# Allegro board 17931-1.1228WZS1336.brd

Outline 227 x 157 mm; copper layers: TOP, L2GND, L3, L4VCC, L5, L6, L7GND, BOTTOM. Coordinates in mm from the lower left corner of the outline.

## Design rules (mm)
constraint set DEFAULT: min track width 0.127, pair gap 0.102
net group 00_POWER_25M: nets PQ3802_1 PSID_DISABLE#_R_C
net group 00_POWER_1600M: nets XVDD_R1 XVDD_R2
net group CRT_DDI_TX_N0: nets CRT_DDI_TX_N0 DP2_DEMUX_OUT2_D0N
net group CRT_DDI_TX_N1: nets CRT_DDI_TX_N1 DP2_DEMUX_OUT2_D1N
net group CRT_DDI_TX_P0: nets CRT_DDI_TX_P0 DP2_DEMUX_OUT2_D0P
net group CRT_DDI_TX_P1: nets CRT_DDI_TX_P1 DP2_DEMUX_OUT2_D1P
net group DDR4_A_BA_40-MW: nets M_A_BA0 M_A_BA1
net group DDR4_A_BG_40-MW: nets M_A_BG0 M_A_BG1
net group DDR4_A_ODT: nets M_A_DIMA_ODT0 M_A_DIMA_ODT1
net group DDR4_B_BA_40-MW: nets M_B_BA0 M_B_BA1
net group DDR4_B_BG_40-MW: nets M_B_BG0 M_B_BG1
net group DDR4_B_ODT: nets M_B_DIMB_ODT0 M_B_DIMB_ODT1
net group DDR4_VREF_40: nets V_SM_VREF_CNTA V_SM_VREF_CNTB
net group DP2_DEMUX_OUT2_D0-DIFF2: nets DP2_DEMUX_OUT2_D0N_R DP2_DEMUX_OUT2_D0P_R
net group DP2_DEMUX_OUT2_D1-DIFF2: nets DP2_DEMUX_OUT2_D1N_R DP2_DEMUX_OUT2_D1P_R
net group DP_AUX_CON-DIFF1: nets DP2_AUX_C_N DP2_AUX_C_P
net group FBA_REFC0: nets FBA_VREFC0 FBA_VREFC1
net group FBA_VREF: nets FBA_VREF_FET_H FBA_VREF_FET_L
net group GFX_PCIE_TX_C_N0: nets GFX_PCIE_TX_C_N0 GFX_PCIE_TX_N0
net group GFX_PCIE_TX_C_N1: nets GFX_PCIE_TX_C_N1 GFX_PCIE_TX_N1
net group GFX_PCIE_TX_C_N2: nets GFX_PCIE_TX_C_N2 GFX_PCIE_TX_N2
net group GFX_PCIE_TX_C_N3: nets GFX_PCIE_TX_C_N3 GFX_PCIE_TX_N3
net group GFX_PCIE_TX_C_P0: nets GFX_PCIE_TX_C_P0 GFX_PCIE_TX_P0
net group GFX_PCIE_TX_C_P1: nets GFX_PCIE_TX_C_P1 GFX_PCIE_TX_P1
net group GFX_PCIE_TX_C_P2: nets GFX_PCIE_TX_C_P2 GFX_PCIE_TX_P2
net group GFX_PCIE_TX_C_P3: nets GFX_PCIE_TX_C_P3 GFX_PCIE_TX_P3
net group GPU_XTAL-DIFF1: nets 27MHZ_IN 27MHZ_OUT
net group HDMI_DDI_TX_CMC_N0: nets HDMI_DDI_TX_CMC_N0 HDMI_DDI_TX_CON_N0
net group HDMI_DDI_TX_CMC_N1: nets HDMI_DDI_TX_CMC_N1 HDMI_DDI_TX_CON_N1
net group HDMI_DDI_TX_CMC_N2: nets HDMI_DDI_TX_CMC_N2 HDMI_DDI_TX_CON_N2
net group HDMI_DDI_TX_CMC_N3: nets HDMI_DDI_TX_CMC_N3 HDMI_DDI_TX_CON_N3
net group HDMI_DDI_TX_CMC_P0: nets HDMI_DDI_TX_CMC_P0 HDMI_DDI_TX_CON_P0
net group HDMI_DDI_TX_CMC_P1: nets HDMI_DDI_TX_CMC_P1 HDMI_DDI_TX_CON_P1
net group HDMI_DDI_TX_CMC_P2: nets HDMI_DDI_TX_CMC_P2 HDMI_DDI_TX_CON_P2
net group HDMI_DDI_TX_CMC_P3: nets HDMI_DDI_TX_CMC_P3 HDMI_DDI_TX_CON_P3
net group LAN_MDI0_N: nets LAN_MDI0_N MDO0-
net group LAN_MDI0_P: nets LAN_MDI0_P MDO0+
net group LAN_MDI1_N: nets LAN_MDI1_N MDO1-
net group LAN_MDI1_P: nets LAN_MDI1_P MDO1+
net group LAN_MDI2_N: nets LAN_MDI2_N MDO2-
net group LAN_MDI2_P: nets LAN_MDI2_P MDO2+
net group LAN_MDI3_N: nets LAN_MDI3_N MDO3-
net group LAN_MDI3_P: nets LAN_MDI3_P MDO3+
net group M_A_CLK0-DIFF184: nets M_A_CLK0 M_A_CLK#0
net group M_A_CLK1-DIFF185: nets M_A_CLK1 M_A_CLK#1
net group M_A_DQS0-DIFF188: nets M_A_DQS_DN0 M_A_DQS_DP0
net group M_A_DQS1-DIFF188: nets M_A_DQS_DN1 M_A_DQS_DP1
net group M_A_DQS2-DIFF188: nets M_A_DQS_DN2 M_A_DQS_DP2
net group M_A_DQS3-DIFF188: nets M_A_DQS_DN3 M_A_DQS_DP3
net group M_A_DQS4-DIFF188: nets M_A_DQS_DN4 M_A_DQS_DP4
net group M_A_DQS5-DIFF188: nets M_A_DQS_DN5 M_A_DQS_DP5
net group M_A_DQS6-DIFF188: nets M_A_DQS_DN6 M_A_DQS_DP6
net group M_A_DQS7-DIFF188: nets M_A_DQS_DN7 M_A_DQS_DP7
net group M_B_CLK0-DIFF186: nets M_B_CLK0 M_B_CLK#0
net group M_B_CLK1-DIFF187: nets M_B_CLK1 M_B_CLK#1
net group M_B_DQS0-DIFF188: nets M_B_DQS_DN0 M_B_DQS_DP0
net group M_B_DQS1-DIFF188: nets M_B_DQS_DN1 M_B_DQS_DP1
net group M_B_DQS2-DIFF188: nets M_B_DQS_DN2 M_B_DQS_DP2
net group M_B_DQS3-DIFF188: nets M_B_DQS_DN3 M_B_DQS_DP3
net group M_B_DQS4-DIFF188: nets M_B_DQS_DN4 M_B_DQS_DP4
net group M_B_DQS5-DIFF188: nets M_B_DQS_DN5 M_B_DQS_DP5
net group M_B_DQS6-DIFF188: nets M_B_DQS_DN6 M_B_DQS_DP6
net group M_B_DQS7-DIFF188: nets M_B_DQS_DN7 M_B_DQS_DP7
net group MEM_SMBCLK: nets MEM_SMBCLK PCH_SMBCLK
net group MEM_SMBDATA: nets MEM_SMBDATA PCH_SMBDATA
net group NONE_PWR2: nets 5V_AUX_S5 PWR_5V_LDO
net group PCIE_RCOMP-DIFF: nets PCIE_RCOMPN PCIE_RCOMPP
net group PWR_CHG_CSINP-DIFF1: nets PWR_CHG_CSIN_RR PWR_CHG_CSIP_RR
net group PWR_CHG_CSINP-DIFF2: nets PWR_CHG_CSIN_R PWR_CHG_CSIP_R
net group PWR_CHG_CSINP-DIFF3: nets PWR_CHG_CSIN PWR_CHG_CSIP
net group PWR_CHG_CSONP-DIFF1: nets PWR_CHG_CSON_RR PWR_CHG_CSOP_RR
net group PWR_CHG_CSONP-DIFF2: nets PWR_CHG_CSON_R PWR_CHG_CSOP_R
net group PWR_CHG_CSONP-DIFF3: nets PWR_CHG_CSON PWR_CHG_CSOP
net group PWR_VCCGT_ISUMNP_GA-DIFF1: nets PWR_VCCGT_ISUMN_GA PWR_VCCGT_ISUMP_GA
net group PWR_VCCGT_ISUMNP_GB-DIFF1: nets PWR_VCCGT_ISUMN_GB PWR_VCCGT_ISUMP_GB
net group PWR_VCCGT_SENSE-DIFF1: nets VCCGT_SENSE VSSGT_SENSE
net group PWR_VCCSA_ISUMNP-DIFF1: nets PWR_VCCSA_ISUMN_R PWR_VCCSA_ISUMP_R
net group PWR_VCCSA_SENSE-DIFF1: nets VCCSA_SENSE VSSSA_SENSE
net group PWR_VCORE_ISUMNP-DIFF1: nets PWR_VCORE_ISUMN_G PWR_VCORE_ISUMP_G
net group PWR_VCORE_SENSE-DIFF1: nets VCCCORE_SENSE VSSCORE_SENSE
net group PWR_VGA_SENSE-DIFF1: nets VGACORE_GND_SENSE_1 VGACORE_VDD_SENSE_1
net group T8-MW: nets CMP_VIN0 CMP_VIN0_R
net group THERM-DIFF1: nets NCT7718_DXN NCT7718_DXP
net group TYPEC_DPB_AUX-DIFF1: nets TYPEC_DP_AUXN TYPEC_DP_AUXP
net group TYPEC_SBU_AUX-DIFF1: nets USB1_SBU1 USB1_SBU2
net group USB4_USB30_RX-DIFF1: nets USB4_USB30_RX_N USB4_USB30_RX_P
net group USB4_USB30_RX-DIFF2: nets USB4_USB30_RX_C_N USB4_USB30_RX_C_P
net group USB4_USB30_RX-DIFF3: nets USB4_USB30_RX_C_R_N USB4_USB30_RX_C_R_P
net group USB4_USB30_TX-DIFF2: nets USB4_USB30_TX_C_N USB4_USB30_TX_C_P
net group USB4_USB30_TX-DIFF3: nets USB4_USB30_TX_N USB4_USB30_TX_P
net group USB4_USB30_TX-DIFF4: nets USB4_USB30_TX_C_R_N USB4_USB30_TX_C_R_P
net group USB_CC_15M: nets USBC1_CC1_CONN USBC1_CC2_CONN
net group VRAM_10M: nets FBA_SEN0 FBA_SEN2
net group VRAM_DQ_45R: nets FBA_CLK0_MIDPT FBA_CLK1_MIDPT
net group WLAN_PCIE10_RX-DIFF1: nets WLAN_PCIE_RX_N10 WLAN_PCIE_RX_P10
net group WLAN_PCIE10_TX-DIFF1: nets WLAN_PCIE_TX_N10 WLAN_PCIE_TX_P10
net group WLAN_PCIE_TX-DIFF1: nets WLAN_PCIE_TX_CON_N WLAN_PCIE_TX_CON_P
net group XDP_CLK-DIFF1: nets XDP_CLK_CPU_N XDP_CLK_CPU_P
net group 00_POWER_5M: nets 3D3V_LAN_CT2 3V5V_CT1 3V5V_CT2 AON_CT_2 AUD_PC_BEEP AUD_PC_BEEP_C BEEP HDA_SPKR_R KBC_BEEP_R LPS_SW LPS_SW_A LPS_SW_C LPS_SW_D SPKR VGA_CT_1 VGA_NVVDD
net group 00_POWER_10M: nets 1D0V_VCCA_XTAL 1D0V_VCCAMPHYPLL 1D0V_VCCDSW +5V_AVDD +SDC_IN_SW_R1 BMON22 CNV_WT_RCOMP FP_3D3V GSENSOR_CS HW_ACAV_IN0 HW_ACAVIN_NB0 I_BATT LDO1_CAP LDO2_CAP LDO3_CAP MIC_CAP PWR_VGA_NVDD_SS PWR_VGA_NVVDD_VSEN PWR_VGA_NVVDD_VSNS/SS
net group 00_POWER_10M_POWER: nets 3D3V_GSEN2 3D3V_MUX 3D3V_MUX2 3D3V_MUX_VCC AC_IN#_G AD_OFF_R AMBER_LED_BAT BAT_AMBER BAT_WHITE LAN_LED0 LAN_LED0_Q LAN_LED0_R PD_VCCD PWR_1D05V_PFM# PWR_1D05V_SS PWR_1D05V_TON PWR_1D35V_BYP PWR_1D35V_IMAX PWR_3D3V_VOUT PWR_5V_VOUT PWR_CHG_ACIN PWR_CHG_ADP/ACIN PWR_CHG_AIN PWR_CHG_AIN_R PWR_CHG_AMON PWR_CHG_ASGATE PWR_CHG_ASGATE/NTC PWR_CHG_BATGONE PWR_CHG_CMRSC PWR_CHG_COMP PWR_CHG_COMP_R PWR_CHG_DCIN PWR_CHG_DCIN_R PWR_CHG_NTC PWR_CHG_OTGEN PWR_CHG_OTGPG PWR_CHG_PROG PWR_CHG_VBAT1 PWR_VCCGT_COMP PWR_VCCGT_COMP1 PWR_VCCGT_FCCM# PWR_VCCGT_FCCM#_RA PWR_VCCGT_FCCM#_RB PWR_VCCGT_IMON PWR_VCCGT_ISEN1 PWR_VCCGT_ISEN2 PWR_VCCGT_ISUMN PWR_VCCGT_ISUMN_P_1 PWR_VCCGT_ISUMN_P_2 PWR_VCCGT_ISUMN_RC PWR_VCCGT_ISUMNB PWR_VCCGT_ISUMP PWR_VCCGT_NTC PWR_VCCGT_NTC1 PWR_VCCGT_PWMA PWR_VCCGT_PWMA_RA PWR_VCCGT_PWMB PWR_VCCGT_PWMB_RA PWR_VCCGT_RTN PWR_VCCSA_COMP PWR_VCCSA_COMP_RC PWR_VCCSA_FCCM PWR_VCCSA_IMON PWR_VCCSA_ISUMN PWR_VCCSA_ISUMN_P_1 PWR_VCCSA_ISUMN_P_2 PWR_VCCSA_ISUMN_RC PWR_VCCSA_ISUMNB PWR_VCCSA_ISUMP PWR_VCCSA_PWM PWR_VCCSA_RTN PWR_VCORE_COMP PWR_VCORE_COMP1 PWR_VCORE_FCCM# PWR_VCORE_FCCM#_R PWR_VCORE_IMON PWR_VCORE_ISUMN PWR_VCORE_ISUMN_P_1 PWR_VCORE_ISUMN_P_2 PWR_VCORE_ISUMN_RC PWR_VCORE_ISUMNA PWR_VCORE_ISUMP PWR_VCORE_NTC PWR_VCORE_NTC1 PWR_VCORE_PROG1 PWR_VCORE_PROG2 PWR_VCORE_PWM PWR_VCORE_PWM_R PWR_VCORE_RTN PWR_VCORE_VR PWR_VDDQ_CS PWR_VDDQ_FB PWR_VDDQ_TON PWR_VDDQ_VDDQ PWR_VGA_CORE_EN# PWR_VGA_CORE_PSI PWR_VGA_CORE_VID PWR_VGA_NVVDD_REFADJ PWR_VGA_NVVDD_REFADJ_R PWR_VGA_NVVDD_REFIN PWR_VGA_NVVDD_REFIN_R PWR_VGA_NVVDD_TON PWR_VGA_NVVDD_TON_1 PWR_VGA_NVVDD_VREF PWR_VGA_NVVDD_VSEN_N PWR_VGA_NVVDD_VSEN_P VDD WHITE_LED_BAT
net group 00_POWER_15M_FB_POWER: nets PWR_1D05V_FB PWR_1D05V_FB_A PWR_1D8V_FB PWR_1D35V_VFB PWR_1D35V_VFB1 PWR_1V_VGA_FB PWR_2D5V_FB PWR_3D3V_FB PWR_3D3V_FB2 PWR_5V_FB PWR_5V_FB_A PWR_VCCGT_FB PWR_VCCGT_FB1 PWR_VCCGT_FB2 PWR_VCCGT_FB_RC PWR_VCCSA_FB PWR_VCCSA_FB1 PWR_VCCSA_FB2 PWR_VCCSA_FB_RC PWR_VCORE_FB PWR_VCORE_FB1 PWR_VCORE_FB2 PWR_VCORE_FB_RC
net group 00_POWER_20M: nets 1D8V_AVDD2 1D24V_VCCDPHY_EC 3D3V_RTC 3D3V_RTC_SYS 3D3V_SPIVCC1 3D3V_TPM 5V_IRLED +RTC_CELL_VBAT +RTC_VCC +V_VREF_PATH2 GPCPLL_AVDD VDD10 VID_PLLVDD VREF_CPU
net group 00_POWER_20M_20M_POWER: nets PWR_1D35V_BOOT_R PWR_3D3V_BOOT PWR_3D3V_BOOT_A PWR_5V_BOOT PWR_5V_BOOT_A PWR_CHG_ASGATE22 PWR_CHG_BGATE PWR_CHG_BGATE_22 PWR_CHG_BT2_R PWR_VCCGT_BOOTA PWR_VCCGT_BOOTA_RC PWR_VCCGT_BOOTB PWR_VCCGT_BOOTB_RC PWR_VCCGT_BOOTRA PWR_VCCGT_BOOTRB PWR_VCCGT_SNB1 PWR_VCCGT_SNB2 PWR_VCCSA_BST PWR_VCCSA_BST_RC PWR_VCORE_BOOT_RC PWR_VCORE_BOOTR PWR_VCORE_SNB PWR_VDDQ_BOOT PWR_VDDQ_BOOTA PWR_VDDQ_BOOTB PWR_VDDQ_SNB PWR_VGA_NVVDD_BOOT1_A PWR_VGA_NVVDD_BOOT2_A
net group 00_POWER_20M_POWER: nets 3D3V_AUX_S5 5V_VCONN_P1_CCG4 +5V_KB_BL CPVDD KB_BL_CTRL# PWR_VCCGT_VCCDA PWR_VCORE_VCC PWR_VCORE_VIN
net group 00_POWER_30M: nets +3V_1D8V_DVDD
net group 00_POWER_30M_20M_POWER: nets PWR_CHG_HG1_R PWR_CHG_HG2_R PWR_CHG_LGATE2 PWR_CHG_SNB
net group 00_POWER_40M: nets 5V_HDMI +1.8VALW_EC DC_IN_OFF FB_CAL_PD_VDDQ FB_CAL_PU_GND FB_CAL_TERM_GND PQ4348_D PU4348_G PWR_VDDQ_VTTREF
net group 00_POWER_80M: nets 1D8V_AON_S0_DISCHG 1D8V_VGA_S0_DISCHG 1D35V_VGA_S0_DISCHG VGA_CORE_DISCHG
net group 3D5MIL_NO_TP: nets FBA_MF1 FBA_MF2 FBA_MF3 FBA_MF4
net group AUDIO_8M: nets MIC2_VREFO
net group AUDIO_12MIL: nets CPVEE
net group AUDIO_12MIL(2): nets AUD_HP1_JACK_L AUD_HP1_JACK_L1 AUD_HP1_JACK_R AUD_HP1_JACK_R1 AUD_PORTA_L_HPMIC1 AUD_PORTA_R_HPMIC1
net group AUDIO_BEEP_10MIL: nets AUD_HPJD_N AUD_SENSE AUD_VREF CBN CBP JACK_PLUG JACK_PLUG_DET LINE1-L_C LINE1-L_R LINE1_L LINE1_R LINE1_VREFO LINE1_VREFO_D1 LINE1_VREFO_D2
net group AUDIO_BITCLK_50-MW: nets HDA_RST_N_CPU
net group AUDIO_SLEEVE_40MIL: nets SLEEVE_R
net group BOT_MUX_N: nets BOT_MUX_N BOT_MUX_N_L BOT_MUX_N_R TOP_MUX_N TOP_MUX_N_L USB1_USB20_N_R
net group BOT_MUX_P: nets BOT_MUX_P BOT_MUX_P_L BOT_MUX_P_R TOP_MUX_P TOP_MUX_P_L USB1_USB20_P_R
net group BT_USB20_CON_N: nets BT_USB20_CON_N
net group BT_USB20_CON_P: nets BT_USB20_CON_P
net group CARD1_USB20_CON_N: nets CARD1_USB20_CON_N
net group CARD1_USB20_CON_P: nets CARD1_USB20_CON_P
net group CLK_50-MWS: nets CLKIN_XTAL_LCP PULSAR_38P4M_REFCLK SUS_CLK SUSACK#_R SUSCLK_WLAN VIDEO_CLK_XTAL_SS
net group CLK_ITE8010: nets CLK_ITE8010 CPU_SMB_SCL_THM GPU_THM_SMBCLK SMBC_THERM_NV SML1_SMBCLK
net group CNV: nets CNV_MFUART2_RXD CNV_MFUART2_TXD CNV_PA_BLANKING
net group COMP_20MIL: nets CFG_RCOMP SM_RCOMP_0 SM_RCOMP_1 SM_RCOMP_2
net group CPU_50-MWS: nets CMP_VOUT0 LPS_SW_R SM_DRAMRST#_CPU TS#_DIMM0_1 TS#_DIMM1_1 VGA_CORE_VID
net group CPU_SMB_SDA_THM: nets CPU_SMB_SDA_THM DAT_ITE8010 GPU_THM_SMBDAT SMBD_THERM_NV SML1_SMBDATA
net group CRT_AUX_CPU_N: nets CRT_AUX_CPU_N CRT_AUX_CPU_N_R IN_AUX_N MUX_CRT_AUX_CPU_N
net group CRT_AUX_CPU_P: nets CRT_AUX_CPU_P CRT_AUX_CPU_P_R IN_AUX_P MUX_CRT_AUX_CPU_P
net group DDR4_A_CMD_40-MW: nets M_A_A0 M_A_A1 M_A_A2 M_A_A3 M_A_A4 M_A_A5 M_A_A6 M_A_A7 M_A_A8 M_A_A9 M_A_A10 M_A_A11 M_A_A12 M_A_A13 M_A_A14 M_A_A15 M_A_A16 M_A_ACT_N M_A_ALERT_N M_A_PARITY
net group DDR4_A_DATA_00_50-MW: nets M_A_DQ0 M_A_DQ1 M_A_DQ2 M_A_DQ3 M_A_DQ4 M_A_DQ5 M_A_DQ6 M_A_DQ7
net group DDR4_A_DATA_01_50-MW: nets M_A_DQ8 M_A_DQ9 M_A_DQ10 M_A_DQ11 M_A_DQ12 M_A_DQ13 M_A_DQ14 M_A_DQ15
net group DDR4_A_DATA_02_50-MW: nets M_A_DQ16 M_A_DQ17 M_A_DQ18 M_A_DQ19 M_A_DQ20 M_A_DQ21 M_A_DQ22 M_A_DQ23
net group DDR4_A_DATA_03_50-MW: nets M_A_DQ24 M_A_DQ25 M_A_DQ26 M_A_DQ27 M_A_DQ28 M_A_DQ29 M_A_DQ30 M_A_DQ31
net group DDR4_A_DATA_04_50--MW: nets M_A_DQ32 M_A_DQ33 M_A_DQ34 M_A_DQ35 M_A_DQ36 M_A_DQ37 M_A_DQ38 M_A_DQ39
net group DDR4_A_DATA_05_50-MW: nets M_A_DQ40 M_A_DQ41 M_A_DQ42 M_A_DQ43 M_A_DQ44 M_A_DQ45 M_A_DQ46 M_A_DQ47
net group DDR4_A_DATA_06_50-MW: nets M_A_DQ48 M_A_DQ49 M_A_DQ50 M_A_DQ51 M_A_DQ52 M_A_DQ53 M_A_DQ54 M_A_DQ55
net group DDR4_A_DATA_07_50-MW: nets M_A_DQ56 M_A_DQ57 M_A_DQ58 M_A_DQ59 M_A_DQ60 M_A_DQ61 M_A_DQ62 M_A_DQ63
net group DDR4_B_CMD_40--MW: nets M_B_A0 M_B_A1 M_B_A2 M_B_A3 M_B_A4 M_B_A5 M_B_A6 M_B_A7 M_B_A8 M_B_A9 M_B_A10 M_B_A11 M_B_A12 M_B_A13 M_B_A14 M_B_A15 M_B_A16 M_B_ACT_N M_B_ALERT_N M_B_PARITY
net group DDR4_B_DATA_00_50-MW: nets M_B_DQ0 M_B_DQ1 M_B_DQ2 M_B_DQ3 M_B_DQ4 M_B_DQ5 M_B_DQ6 M_B_DQ7
net group DDR4_B_DATA_01_50-MW: nets M_B_DQ8 M_B_DQ9 M_B_DQ10 M_B_DQ11 M_B_DQ12 M_B_DQ13 M_B_DQ14 M_B_DQ15
net group DDR4_B_DATA_02_50-MW: nets M_B_DQ16 M_B_DQ17 M_B_DQ18 M_B_DQ19 M_B_DQ20 M_B_DQ21 M_B_DQ22 M_B_DQ23
net group DDR4_B_DATA_03_50-MW: nets M_B_DQ24 M_B_DQ25 M_B_DQ26 M_B_DQ27 M_B_DQ28 M_B_DQ29 M_B_DQ30 M_B_DQ31
net group DDR4_B_DATA_04_50-MW: nets M_B_DQ32 M_B_DQ33 M_B_DQ34 M_B_DQ35 M_B_DQ36 M_B_DQ37 M_B_DQ38 M_B_DQ39
net group DDR4_B_DATA_05_50-MW: nets M_B_DQ40 M_B_DQ41 M_B_DQ42 M_B_DQ43 M_B_DQ44 M_B_DQ45 M_B_DQ46 M_B_DQ47
net group DDR4_B_DATA_06_50-MW: nets M_B_DQ48 M_B_DQ49 M_B_DQ50 M_B_DQ51 M_B_DQ52 M_B_DQ53 M_B_DQ54 M_B_DQ55
net group DDR4_B_DATA_07_50-MW: nets M_B_DQ56 M_B_DQ57 M_B_DQ58 M_B_DQ59 M_B_DQ60 M_B_DQ61 M_B_DQ62 M_B_DQ63
net group DDR4_CKE: nets M_A_CKE0 M_A_CKE1 M_A_CS#0 M_A_CS#1 M_B_CKE0 M_B_CKE1 M_B_CS#0 M_B_CS#1
net group DGPU_TXN_CPU_RXN0: nets DGPU_TXN_CPU_RXN0
net group DGPU_TXN_CPU_RXN1: nets DGPU_TXN_CPU_RXN1
net group DGPU_TXN_CPU_RXN2: nets DGPU_TXN_CPU_RXN2
net group DGPU_TXN_CPU_RXN3: nets DGPU_TXN_CPU_RXN3
net group DGPU_TXP_CPU_RXP0: nets DGPU_TXP_CPU_RXP0
net group DGPU_TXP_CPU_RXP1: nets DGPU_TXP_CPU_RXP1
net group DGPU_TXP_CPU_RXP2: nets DGPU_TXP_CPU_RXP2
net group DGPU_TXP_CPU_RXP3: nets DGPU_TXP_CPU_RXP3
net group DIMM_SA: nets SA0_CHA_DIM0 SA0_CHB_DIM0 SA1_CHA_DIM0 SA1_CHB_DIM0 SA2_CHA_DIM0 SA2_CHB_DIM0
net group DP2_DDI_TX_C_N2: nets DP2_DDI_TX_C_N2 DP2_DDI_TX_C_N2_R DP2_DDI_TX_RE_C_N2 TYPEC_DP_N2 TYPEC_DP_N2_C
net group DP2_DDI_TX_C_N3: nets DP2_DDI_TX_C_N3 DP2_DDI_TX_C_N3_R DP2_DDI_TX_RE_C_N3 TYPEC_DP_N3 TYPEC_DP_N3_C
net group DP2_DDI_TX_C_P2: nets DP2_DDI_TX_C_P2 DP2_DDI_TX_C_P2_R DP2_DDI_TX_RE_C_P2 TYPEC_DP_P2 TYPEC_DP_P2_C
net group DP2_DDI_TX_C_P3: nets DP2_DDI_TX_C_P3 DP2_DDI_TX_C_P3_R DP2_DDI_TX_RE_C_P3 TYPEC_DP_P3 TYPEC_DP_P3_C
net group DP2_DDI_TX_N0: nets DP2_DDI_TX_R_N0 DP2_DDI_TX_R_N0_R DP2_DDI_TX_RE_C_N0 TYPEC_DP_N0 TYPEC_DP_N0_C
net group DP2_DDI_TX_N1: nets DP2_DDI_TX_R_N1 DP2_DDI_TX_R_N1_R DP2_DDI_TX_RE_C_N1 TYPEC_DP_N1 TYPEC_DP_N1_C
net group DP2_DDI_TX_P0: nets DP2_DDI_TX_R_P0 DP2_DDI_TX_R_P0_R DP2_DDI_TX_RE_C_P0 TYPEC_DP_P0 TYPEC_DP_P0_C
net group DP2_DDI_TX_P1: nets DP2_DDI_TX_R_P1 DP2_DDI_TX_R_P1_R DP2_DDI_TX_RE_C_P1 TYPEC_DP_P1 TYPEC_DP_P1_C
net group EDP_AUX_CON_N: nets EDP_AUX_CON_N
net group EDP_AUX_CON_P: nets EDP_AUX_CON_P
net group EDP_TX_CON_N0: nets EDP_TX_CON_N0
net group EDP_TX_CON_N1: nets EDP_TX_CON_N1
net group EDP_TX_CON_P0: nets EDP_TX_CON_P0
net group EDP_TX_CON_P1: nets EDP_TX_CON_P1
net group EPSI_50: nets ESPI_ALERT#
net group GND: nets U9101_2_GND
net group HDA_BITCLK_CODEC: nets HDA_BITCLK_CODEC_R
net group HDD2_SATA_RX_CON_N: nets HDD2_SATA_RX_CON_N
net group HDD2_SATA_RX_CON_P: nets HDD2_SATA_RX_CON_P
net group HDD2_SATA_TX_CON_N: nets HDD2_SATA_TX_CON_N
net group HDD2_SATA_TX_CON_P: nets HDD2_SATA_TX_CON_P
net group KBC: nets KSI0 KSI1 KSI2 KSI3 KSI4 KSI5 KSI6 KSI7 KSO0 KSO1 KSO2 KSO3 KSO4 KSO5 KSO6 KSO7 KSO8 KSO9 KSO10 KSO11 KSO12 KSO13 KSO14 KSO15 KSO16
net group LAN_6M: nets RSET
net group LAN_PCIE_RX_C_N: nets LAN_PCIE_RX_C_N
net group LAN_PCIE_RX_C_P: nets LAN_PCIE_RX_C_P
net group LAN_PCIE_TX_N: nets LAN_PCIE_TX_N_C
net group LAN_PCIE_TX_P: nets LAN_PCIE_TX_P_C
net group LED: nets BAT2_LED# CAP_LED# CAP_LED#_R PWR_LED# PWR_LED#_C PWR_LED#_Q PWR_LED#_R SATA_LED# SATA_LED#_D
net group LED_20MIL: nets C10_GATE CAP_LED CAP_LED_Q
net group ODD_SATA_RX_CON_N: nets ODD_SATA_RX_CON_N
net group ODD_SATA_RX_CON_P: nets ODD_SATA_RX_CON_P
net group ODD_SATA_TX_CON_N: nets ODD_SATA_TX_CON_N
net group ODD_SATA_TX_CON_P: nets ODD_SATA_TX_CON_P
net group OTHER_4MIL: nets 1D05V_S5_PWRGD 1D8V_AON_EN 1D8V_MAIN_EN 1D8V_MAIN_EN_D 1D8V_MAIN_EN_R 1D8V_MAIN_ENABLE 1D8V_VGA_DISC 1D35V_PGOOD 1D35V_VGA_EN# 1V_VGA_S0_EN 1V_VGA_S0_PG 3D3V_CAMERA_CT1 3D3V_TP_CT2 3V_5V_DSW_OK 3V_5V_EN 3V_5V_POK# 5V_VCONN_EN 20V_VCCPD_VBUS_R AC_DIS AC_PRESENT ACOK_IN_M AD_IA AD_OFF_L ALERT# ALWON AUX_EN_WOWL AUX_EN_WOWL_R AUX_ON BAT1_LED# BATT_WHITE_LED# BATT_WHITE_LED#_Q BKLT_CTRL BKLT_IN_EC BLON_OUT_C BLUETOOTH_EN BLUETOOTH_EN_R BOARD_ID BOARD_ID1 BPM_CPU_N0 BPM_CPU_N1 BPM_CPU_N2 BPM_CPU_N3 BREATH_LED# BT_PCMOUT_CLKREQ0 CAD_SNK_MUX CAM_EN CATERR#_CPU CCG4_FLIP# CCG4_I2C_INT# CCG4_ID_1 CFG0_DP_MUX CFG3 CFG4 CHG_AMBER_LED# CHG_AMBER_LED#_Q CHGR_PSYS_IMVP CLK_PCIE_LAN_REQ# CLK_PCIE_NVME_REQ# CLK_PCIE_PEG_REQ# CLK_PCIE_SD_REQ# CLK_PCIE_WLAN_REQ# CNVI_EN# CNVI_EN#_R CPU_DP1_HPD CPU_DP2_HPD CPU_DP_HPD_MUX CPU_DP_HPD_R CRT_DP_HPD CRT_DP_HPD_R CTL1 CTL2 CTL3 DBC_EN_R DBC_PANEL_EN DCBATOUT_LCD_PG DCBATOUT_LCD_PWRGD DDR4_DRAMRST# DGPU_HOLD_RST# DGPU_PWR_EN DGPU_PWR_EN_1 DGPU_PWR_EN_2 DGPU_PWROK DOCK_USB_EN_A DOCK_USB_EN_B DP2_HPD_CPU DPEQ0_A1 DPEQ1 EC_D_INHIB EDP_FHD_DET# EDP_FHD_DET#_R EDP_HPD EDP_HPD_CONN EDP_VDD_EN EQ0 EQ1 EXT_PWR_GATE# FALL_INT2 FBA_DEBUG0 FBA_DEBUG1 FFS_INT1 FFS_INT2 FFS_INT2_Q FLT_NXP3290 FP_EN# FPR_SCAN# GC6_FB_EN_GPU GC6_FB_EN_GPU_L GC6_FB_EN_GPU_R GC6_FB_EN_MCP GC6_THM_DIS GC6_THM_DIS#_EC GC6_THM_DIS#_PCH GPD11/LANPHYPC GPD_7 GPIO5_FRAME_LOCK# GPIO9_ALERT GPIO10_FBVREF GPIO11_LCD_VDD GPIO13_LCD_BLEN GPP_E23_STRAP GPP_H2_CLKREQ0 GPP_H21 GPP_H23 GPPC_H18_VCCIO_LPM GPU_CLKREQ# GPU_EVENT_GPU# GPU_EVENT_GPU#_R GPU_EVENT_MCP# GPU_PEX_RST# GPU_PEX_RST_HOLD GPU_PEX_RST_HOLD_GPU# GPU_ROM GSENSOR_SDO H_CPUPWRGD HDD_DET# HDD_DEVSLP HDD_DEVSLP_R HDMI_HPD_B HDMI_HPD_CON HOST_DEBUG_TX HOST_DEBUG_TX_CON HPDIN HW_ACAV_IN HW_ACAVIN_NB I2C_CTL_EN I2CEN I_ADP IC_DELAY ICSP_CLR ILIM_HI ILIM_LO ILIM_SEL INPUT3VSEL INT#_ITE8010 IO_DB_DET# IO_DB_DET#_EC IO_DB_DET#_GPPG5 IO_DB_DET#_R IR_CAM_DET# ISOLATE# IST_TRIG ITP_PMODE JIO3_PCIE_WAKE# KB_DET# KB_LED_BL_DET KB_LED_DET_C KB_LED_PWM KBC_PWRBTN# KBC_PWRBTN#_C L_BKLT_CTRL L_BKLT_EN L_BKLT_EN_L LAN_CABLE_DETECT_R_# LAN_WAKE# LANWAKE# LCD_BRIGHTNESS LCD_CBL_DET# LCD_TST LCD_TST_C LCD_VCC_TEST_EN LCDVDD_EN LCDVDD_PG LCDVDD_PWRGD LID_CL_SIO# LID_CLOSE#_C LOM_CABLE_DETECT# LOM_TCT M2_PCIE_LED# M2_SSD_PEDET MASK_SATA_LED# MCT MCT0 MCT1 MCT2 MCT3 ME_FWP ME_FWP_R ME_SUS_PWR_ACK_R MESW1_B MODEL_ID MSATA_DEVSLP_R MUX_HPD_PD MUX_SAI MUX_SAO MUX_SBI MUX_SBO N12P_JTAG_TCK N12P_JTAG_TDI N12P_JTAG_TDO N12P_JTAG_TMS N12P_JTAG_TRST N12P_XTAL_OUTBUFF N92950396 NB_MUTE# NC_AUX_EN_WOWL_EC NRB_BIT NUVOTON_PP NVVDD_EN NVVDD_EN_1 NXP3290_FO NXP3290_ILIM NXP3290CAP OUT1_CA_DET OUT2_CA_DET OVERT_GPU# PANEL_BKEN PANEL_BKEN_EC PANEL_MONITOR PANEL_PWRGD_R PBAT_PRES1# PBAT_PRES# PC10 PC11 PC20 PC21 PCH_BATLOW# PCH_PLTRST# PCH_RSMRST# PCH_TPAN_VDD_EN PCH_WAKE# PCIE_LAN_WAKE# PCIE_WAKE# PD4403_A PD4403_K PD_SWD_CLK PD_VBUS_C_CTRL1 PD_VBUS_C_CTRL1_A PD_VBUS_C_CTRL1_R PD_VBUS_C_EN_A PD_VBUS_C_EN_B PD_VBUS_DISCHG PD_VBUS_DISCHG_N1 PD_XRES PDB_R PEQ PEX_TERMP PEX_TSTCLK_OUT PEX_TSTCLK_OUT# PIRQA# PLTRST#_CPU PM_LAN_ENABLE PM_RSMRST# PM_RSMRST#_M POWER_SW_IN# PQ4405_2 PQ4405_3 PQ4405_5 PQ4405_6 PQ4408_C PQ4408_E PQ4417_D PQ4417_G PQ4418_2 PQ4418_3 PQ4418_5 PQ4418_6 PRIM_PWRGD PROCHOT PROCHOT#_CPU PROCHOT#_CPU_R PROJECT_ID0 PROJECT_ID1 PROJECT_ID2 PROJECT_ID3 PTP_DIS# PURE_HW_SHUTDOWN# PWR_1D05V_EN PWR_1D8V_EN PWR_1D8V_PG PWR_1D35V_PGOOD PWR_2D5V_EN PWR_2D5V_PG PWR_3D3V_EN PWR_3D3V_EN1 PWR_5V_EN PWR_5V_EN1 PWR_BD_DET# PWR_CHG_ACOK PWR_CHG_PSYS PWR_LEVEL PWR_VDDQ_EN PWR_VDDQ_PG PWR_VGA_GDDR_EN PWR_VGA_GDDR_EN_L PWR_VGA_NVVDD_EN PWR_VGA_NVVDD_EN_R PWR_VGA_NVVDD_PG Q501_G Q5503_B Q5503_C Q5503_E Q5504_B Q5504_C Q5505_E Q6407_B Q6407_C RESET_OUT# RSMRST_PWRGD# RTC_3P3_EN_G RTC_DET# RTCRST_ON RUNPWROK SATA1_ODD_PRSNT# SATA_ODD_DA#_C SATA_ODD_PRSNT#_R SD_READ_MODE# SD_READ_MODE#_R SIO_EXT_SMI# SIO_EXT_WAKE# SIO_PWRBTN# SIO_RCIN# SIO_SLP_A# SIO_SLP_S0# SIO_SLP_S3# SIO_SLP_S4# SIO_SLP_S5# SKTOCC# SM_INTRUDER# SM_PGCNTL SM_PGCNTL_Q SSD2_DEVSLP SSD_DEVSLP SSD_DEVSLP_R SSD_SCP# SSEQ0_A0 SSEQ1 ST_GPIO ST_PP STRAP0 STRAP1 STRAP2 STRAP3 STRAP4 STRAP5 STRAP5_R STRAP_REF0_GND_N9 SW_PIN SYS_LED_MASK# SYS_PEX_RST_MON# SYS_PEX_RST_MON_GPU# SYS_PRES1# SYS_PWROK SYSPWR_PRES T_CRIT# TESTMODE THERM_SYS_SHDN# THERMTRIP#_CPU TOUCH_I2C_DET# TOUCH_PAD_INTR# TOUCH_PANEL_INTR# TOUCH_PANEL_PD# TOUCH_REPORT_SW TP_EN# TP_ON#_GATE TP_WAKE_KBC# TPAN_VDD_EN_R TPM_GPIO0 TPM_GPIO1 TPM_GPIO4 TPM_ID TPM_SPI_IRQ# TPS2544_FAULT# TPS70933_EN TPS70933_EN_G TS_INT# TS_VREF TYPEC_DCIN1_EN# USB2_ID USB2_VBUSSENSE USB_EN# USB_OC0# USB_OC1# USB_OC1#_R USB_OC2# USB_OC3# USB_POWERSHARE_VBUS_EN USB_PWR_SHR_EN_L# V0.85A_VID0 V0.85A_VID1 VBUS_P_CTRL VBUS_P_CTRL_R VCCDSW_ON VCCPD_VBUS_ACK VCCST_PWRGD_R VCCSTG_EN_R1 VCCSTU_EN_R VCI_IN1# VDDQ_PWRGD VGA_CORE_VID_R VGA_DB_DET# VGA_DB_DET#_R VGA_PWR_EN# VR_EN VR_RDY VRALERT# VRAM_ID1 VRAM_ID2 WIFI_RF_EN WIFI_RF_EN_R WLAN_EN# WWAN_BB_RST# WWAN_CLKREQ_CPU_N WWAN_DB_DET# WWAN_DB_DET#_R WWAN_FULL_PWR_EN WWAN_FULL_PWR_EN_D8 WWAN_FULL_PWR_EN_R WWAN_GPIO_PERST# WWAN_PCIE_WAKE_N
net group POWER_10M: nets FB_CLAM
net group REF10M: nets VR_CAP
net group SIGNAL_V_F_5MIL: nets 1D8V_S0_CT1 ACOK# CEXT EDP_RCOMP_CPU EMMC_RCOMP FAN1_PWM FAN1_TACH FAN_PWM1_C FAN_TACH1 FAN_TACH1_C FBA_ZQ0 FBA_ZQ1 FBA_ZQ2 FBA_ZQ3 GPU_PWR_LEVEL PWR_CHG_PROCHOT# PWR_VCORE_VRHOT# Q6205_Q REXT1 RTC_RST# SD_RCOMP SRTC_RST# V3D3_STB XCLK_BIASREF
net group SIGNAL_V_F_10MIL-2: nets PS_ID PS_ID_R1 VCCRTCEXT VCREF0
net group SIGNAL_V_F_25MIL: nets HDMI_PLL_GND
net group SMBUS: nets BT_PCMFRM_RSTN CCG4_I2C_SCL CCG4_I2C_SDA CLK_TP_SIO CPU_DP2_CTRL_CLK CPU_DP2_CTRL_DATA CPU_POPIRCOMP DAT_TP_SIO DMIC_CLK_EDP DMIC_DATA_EDP DMIC_PCH_CLK DMIC_PCH_DATA DMIC_SCL_CODEC DMIC_SCL_CODEC_R DMIC_SDA_CODEC GPP_H1_SFRM GPU_I2CA_SCL GPU_I2CA_SDA HDMI_SCL_R HDMI_SDA_R I2C0_SCL_TCH_PAD I2C0_SCL_TCH_PNL I2C0_SDA_TCH_PAD I2C0_SDA_TCH_PNL I2C1_SCL_R I2C1_SDA_R I2C_CLK I2C_CLK_PD I2C_CLK_PD_MUX I2C_DATA_PD I2C_DATA_PD_MUX I2C_SDA I2CB_SCL I2CB_SDA I2CC_SCL I2CC_SDA ICSP_CLK ICSP_DAT PBAT_CHG_SMBCLK PBAT_CHG_SMBDAT PBAT_SMBCLK1 PBAT_SMBDAT1 PCH_JTAG_TCK PCH_JTAG_TDI PCH_JTAG_TDO PCH_JTAG_TMS PCH_POPIRCOMP SMB_ALERT# SML0_ALERT# SML0_SMBCLK SML0_SMBDATA SML1ALERT# TPCLK_C TPDATA_C TYPEC_SMBCLK TYPEC_SMBDA UART_2_CRXD_DTXD UART_2_CRXD_DTXD_CON UART_2_CTXD_DRXD UART_2_CTXD_DRXD_CON USBCOMP
net group SPI_50-MWS: nets GPU_ROM_SCLK GPU_ROM_SI GPU_ROM_SO SPI_CS2#_IC SPI_CS_CPU_N0 SPI_CS_CPU_N1 SPI_CS_CPU_N2 SPI_IRQ#_TPM2
net group SPI_CLK_CPU: nets SPI_CLK_CPU SPI_CLK_ROM SPI_CLK_ROM2 SPI_CLK_ROM_TPM
net group SPI_HOLD_CPU: nets SPI_HOLD_CPU SPI_HOLD_ROM SPI_HOLD_ROM2
net group SPI_SI_CPU: nets SPI_SI_CPU SPI_SI_ROM SPI_SI_ROM2 SPI_SI_ROM_TPM
net group SPI_SO_CPU: nets SPI_SO_CPU SPI_SO_ROM SPI_SO_ROM2 SPI_SO_ROM_TPM
net group SPI_WP_CPU: nets SPI_WP_CPU SPI_WP_ROM SPI_WP_ROM2
net group SSD_PCIE_TX_CON_N13: nets SSD_PCIE_TX_CON_N13
net group SSD_PCIE_TX_CON_N14: nets SSD_PCIE_TX_CON_N14
net group SSD_PCIE_TX_CON_N15: nets SSD_PCIE_TX_CON_N15
net group SSD_PCIE_TX_CON_P13: nets SSD_PCIE_TX_CON_P13
net group SSD_PCIE_TX_CON_P14: nets SSD_PCIE_TX_CON_P14
net group SSD_PCIE_TX_CON_P15: nets SSD_PCIE_TX_CON_P15
net group SSD_PCIE_TX_N16: nets SSD_SATA_TX_CON_N16
net group SSD_PCIE_TX_P16: nets SSD_SATA_TX_CON_P16
net group SVID: nets GPIO6_VGA_CORE_PSI H_PECI PECI_CPU VGA_CORE_PSI
net group SVID_ALERT#_CPU: nets SVID_ALERT#_VR
net group SVID_CLK_CPU: nets SVID_CLK_VR
net group SVID_DATA_CPU: nets SVID_DATA_VR
net group USB1_SSRX_CMC_N1: nets USB1_SSRX_CMC_N1
net group USB1_SSRX_CMC_N2: nets USB1_SSRX_CMC_N2
net group USB1_SSRX_CMC_P1: nets USB1_SSRX_CMC_P1
net group USB1_SSRX_CMC_P2: nets USB1_SSRX_CMC_P2
net group USB1_SSTX_CMC_N1: nets USB1_SSTX_C_N1
net group USB1_SSTX_CMC_N2: nets USB1_SSTX_C_N2
net group USB1_SSTX_CMC_P1: nets USB1_SSTX_C_P1
net group USB1_SSTX_CMC_P2: nets USB1_SSTX_C_P2
net group USB2_USB20_N: nets USB2_USB20_N_CMC
net group USB2_USB20_P: nets USB2_USB20_P_CMC
net group USB3_CHAR_2544_N: nets USB3_CHAR_2544_N USB3_NONPS_N USB3_USB20_2544_N
net group USB3_CHAR_2544_P: nets USB3_CHAR_2544_P USB3_CHAR_P USB3_NONPS_P USB3_USB20_2544_P
net group USB3_USB30_RX_CON_N: nets USB3_USB30_RX_CON_N
net group USB3_USB30_RX_CON_P: nets USB3_USB30_RX_CON_P
net group USB3_USB30_TX_CMC_N: nets USB3_USB30_TX_CMC_N
net group USB3_USB30_TX_CMC_P: nets USB3_USB30_TX_CMC_P
net group USB4_USB20_CON_N: nets USB4_USB20_CON_N
net group USB4_USB20_CON_P: nets USB4_USB20_CON_P
net group USB4_USB30_RX_CON_N: nets USB4_USB30_RX_CON_N
net group USB4_USB30_RX_CON_P: nets USB4_USB30_RX_CON_P
net group VRAM_CMD_45R-MWS: nets FBA_CMD0 FBA_CMD1 FBA_CMD2 FBA_CMD3 FBA_CMD4 FBA_CMD5 FBA_CMD6 FBA_CMD7 FBA_CMD8 FBA_CMD9 FBA_CMD10 FBA_CMD11 FBA_CMD12 FBA_CMD13 FBA_CMD14 FBA_CMD15 FBA_CMD16 FBA_CMD17 FBA_CMD18 FBA_CMD19 FBA_CMD20 FBA_CMD21 FBA_CMD22 FBA_CMD23 FBA_CMD24 FBA_CMD25 FBA_CMD26 FBA_CMD27 FBA_CMD28 FBA_CMD29 FBA_CMD30 FBA_CMD31
net group WWAN_PCIE_TX_N: nets WWAN_PCIE_TX_N_C
net group WWAN_PCIE_TX_P: nets WWAN_PCIE_TX_P_C
net group WWAN_USB20_N: nets WWAN_USB20_N_R
net group WWAN_USB20_P: nets WWAN_USB20_P_R
net group XDP: nets XDP_DBRESET# XDP_PRDY# XDP_PREQ# XDP_TCK_JTAGX XDP_TCLK XDP_TDI XDP_TDO_CPU XDP_TMS XDP_TRST#
net group XTAL-MW: nets 27MHZ_OUT_R LANXIN LANXOUT MEC_XTAL1_R MEC_XTAL2 XTL_24M_X1_CPU XTL_24M_X1_R XTL_24M_X2_CPU XTL_24M_X2_R XTL_32K_X1_CPU XTL_32K_X2_CPU

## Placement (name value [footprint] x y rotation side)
AFTP2601  AFTE14P-GP  [AFTE14P-75]  158.37 86.69 90 top
AFTP2602  AFTE14P-GP  [AFTE14P-75]  158.37 84.79 90 top
AFTP2603  AFTE14P-GP  [AFTE14P-75]  160.79 88.7 90 top
AFTP2604  AFTE14P-GP  [AFTE14P-75]  128.53 107.72 90 top
AFTP2901  AFTE14P-GP  [AFTE14P-75]  7.8 5.36 180 top
AFTP2902  AFTE14P-GP  [AFTE14P-75]  9.75 5.89 180 top
AFTP2903  AFTE14P-GP  [AFTE14P-75]  11.36 4.37 90 top
AFTP2904  AFTE14P-GP  [AFTE14P-75]  12.04 2.34 90 top
AFTP3201  AFTE14P-GP  [AFTE14P-75]  22.95 86.51 0 bottom
AFTP3202  AFTE14P-GP  [AFTE14P-75]  26.37 81.26 0 bottom
AFTP3204  AFTE14P-GP  [AFTE14P-75]  23.9 88.34 0 bottom
AFTP3205  AFTE14P-GP  [AFTE14P-75]  26.24 84.23 180 top
AFTP3206  AFTE14P-GP  [AFTE14P-75]  25.87 81.68 180 top
AFTP3207  AFTE14P-GP  [AFTE14P-75]  19.56 80.06 180 top
AFTP3208  AFTE14P-GP  [AFTE14P-75]  24.46 81.19 0 bottom
AFTP3209  AFTE14P-GP  [AFTE14P-75]  18.9 78.26 180 top
AFTP3502  AFTE14P-GP  [AFTE14P-75]  17.53 48.21 90 top
AFTP3503  AFTE14P-GP  [AFTE14P-75]  16.34 49.71 90 top
AFTP3507  AFTE14P-GP  [AFTE14P-75]  21.87 55.81 180 bottom
AFTP3508  AFTE14P-GP  [AFTE14P-75]  17.22 35.38 0 top
AFTP4302  AFTE14P-GP  [AFTE14P-75]  19.23 127.97 0 top
AFTP4303  AFTE14P-GP  [AFTE14P-75]  21.52 124.28 180 top
AFTP4304  AFTE14P-GP  [AFTE14P-75]  19.61 124.28 90 top
AFTP4306  AFTE14P-GP  [AFTE14P-75]  175.19 35.74 0 top
AFTP4307  AFTE14P-GP  [AFTE14P-75]  199.65 36.88 0 top
AFTP4309  AFTE14P-GP  [AFTE14P-75]  139.7 34.47 180 top
AFTP4310  AFTE14P-GP  [AFTE14P-75]  140.64 36.93 180 top
AFTP4311  AFTE14P-GP  [AFTE14P-75]  142.57 36.7 180 top
AFTP4312  AFTE14P-GP  [AFTE14P-75]  144.53 36.63 0 top
AFTP4313  AFTE14P-GP  [AFTE14P-75]  174.07 31.68 0 top
AFTP4315  AFTE14P-GP  [AFTE14P-75]  137.82 33.76 180 top
AFTP4401  AFTE14P-GP  [AFTE14P-75]  171.91 35.79 180 bottom
AFTP4402  AFTE14P-GP  [AFTE14P-75]  171.76 31.34 180 bottom
AFTP4403  AFTE14P-GP  [AFTE14P-75]  178.79 34.77 180 bottom
AFTP4404  AFTE14P-GP  [AFTE14P-75]  177.02 37.52 180 bottom
AFTP4405  AFTE14P-GP  [AFTE14P-75]  177.3 42.34 180 bottom
AFTP4406  AFTE14P-GP  [AFTE14P-75]  175.11 37.52 180 bottom
AFTP4407  AFTE14P-GP  [AFTE14P-75]  181.82 58.45 180 bottom
AFTP4408  AFTE14P-GP  [AFTE14P-75]  189.26 58.68 180 bottom
AFTP4501  AFTE14P-GP  [AFTE14P-75]  49 39.17 0 top
AFTP4502  AFTE14P-GP  [AFTE14P-75]  50.27 40.62 0 top
AFTP4601  AFTE14P-GP  [AFTE14P-75]  63.25 128.2 0 top
AFTP4602  AFTE14P-GP  [AFTE14P-75]  62.36 129.72 0 top
AFTP4603  AFTE14P-GP  [AFTE14P-75]  88.78 129.21 0 top
AFTP4604  AFTE14P-GP  [AFTE14P-75]  87.76 130.35 0 top
AFTP4605  AFTE14P-GP  [AFTE14P-75]  96.27 130.74 0 top
AFTP4606  AFTE14P-GP  [AFTE14P-75]  97.79 129.59 0 top
AFTP5001  AFTE14P-GP  [AFTE14P-75]  92.64 138.28 0 top
AFTP5501  AFTE14P-GP  [AFTE14P-75]  168.41 71.83 270 top
AFTP5502  AFTE14P-GP  [AFTE14P-75]  170.97 34.44 270 top
AFTP5503  AFTE14P-GP  [AFTE14P-75]  178.06 70.31 270 top
AFTP5504  AFTE14P-GP  [AFTE14P-75]  169.45 35.71 270 top
AFTP5505  AFTE14P-GP  [AFTE14P-75]  168.68 41.66 270 top
AFTP5506  AFTE14P-GP  [AFTE14P-75]  167.57 35.03 270 top
AFTP5509  AFTE14P-GP  [AFTE14P-75]  212.12 42.8 270 top
AFTP5510  AFTE14P-GP  [AFTE14P-75]  213.97 44.88 270 top
AFTP5511  AFTE14P-GP  [AFTE14P-75]  215.4 43.49 270 top
AFTP5512  AFTE14P-GP  [AFTE14P-75]  218.98 42.01 270 top
AFTP5513  AFTE14P-GP  [AFTE14P-75]  182.1 69.93 270 top
AFTP5514  AFTE14P-GP  [AFTE14P-75]  136.91 35.46 270 top
AFTP5517  AFTE14P-GP  [AFTE14P-75]  215.17 41.58 270 top
AFTP5521  AFTE14P-GP  [AFTE14P-75]  220.09 39.04 270 top
AFTP5522  AFTE14P-GP  [AFTE14P-75]  214.3 63.32 270 top
AFTP5523  AFTE14P-GP  [AFTE14P-75]  218.19 38.96 270 top
AFTP5525  AFTE14P-GP  [AFTE14P-75]  219.21 37.34 270 top
AFTP5601  AFTE14P-GP  [AFTE14P-75]  203.08 62.54 0 top
AFTP5602  AFTE14P-GP  [AFTE14P-75]  175.82 47.68 0 top
AFTP6001  AFTE14P-GP  [AFTE14P-75]  187.43 41.63 0 top
AFTP6002  AFTE14P-GP  [AFTE14P-75]  191.52 41.96 0 top
AFTP6003  AFTE14P-GP  [AFTE14P-75]  189.31 40.92 0 top
AFTP6004  AFTE14P-GP  [AFTE14P-75]  187.4 39.68 0 top
AFTP6005  AFTE14P-GP  [AFTE14P-75]  186.06 38.13 0 top
AFTP6006  AFTE14P-GP  [AFTE14P-75]  183.39 34.72 0 top
AFTP6108  AFTE14P-GP  [AFTE14P-75]  42.52 103.1 180 top
AFTP6109  AFTE14P-GP  [AFTE14P-75]  42.76 96.07 0 top
AFTP6110  AFTE14P-GP  [AFTE14P-75]  41.79 101.32 180 top
AFTP6111  AFTE14P-GP  [AFTE14P-75]  29.75 97.74 0 top
AFTP6112  AFTE14P-GP  [AFTE14P-75]  40.67 103.81 180 top
AFTP6113  AFTE14P-GP  [AFTE14P-75]  31.5 101.65 90 top
AFTP6114  AFTE14P-GP  [AFTE14P-75]  30.13 95.86 0 top
AFTP6115  AFTE14P-GP  [AFTE14P-75]  41.25 94.74 180 top
AFTP6401  AFTE14P-GP  [AFTE14P-75]  210.06 56.85 270 top
AFTP6402  TPAD14-OP-GP  [TPAD14-OP]  210.57 58.62 0 top
AFTP6403  AFTE14P-GP  [AFTE14P-75]  206.2 54.76 270 top
AFTP6404  AFTE14P-GP  [AFTE14P-75]  208.44 55.83 270 top
AFTP6407  AFTE14P-GP  [AFTE14P-75]  213.64 56.49 0 top
AFTP6408  AFTE14P-GP  [AFTE14P-75]  211.48 60.28 0 top
AFTP6501  AFTE14P-GP  [AFTE14P-75]  107.93 35.79 0 top
AFTP6524  AFTE14P-GP  [AFTE14P-75]  108.72 33.83 180 top
AFTP6525  AFTE14P-GP  [AFTE14P-75]  106.51 37.16 0 top
AFTP6526  AFTE14P-GP  [AFTE14P-75]  107.19 32.49 0 top
AFTP6527  AFTE14P-GP  [AFTE14P-75]  104.52 33.71 0 top
AFTP6528  AFTE14P-GP  [AFTE14P-75]  106.3 34.47 0 top
AFTP6529  AFTE14P-GP  [AFTE14P-75]  100.46 28.75 0 top
AFTP6530  AFTE14P-GP  [AFTE14P-75]  110.62 33.83 0 top
AFTP6531  AFTE14P-GP  [AFTE14P-75]  74.81 35.69 180 top
AFTP6537  AFTE14P-GP  [AFTE14P-75]  79.68 32.38 0 top
AFTP6541  AFTE14P-GP  [AFTE14P-75]  76.08 34.24 0 top
AFTP6542  AFTE14P-GP  [AFTE14P-75]  56.77 29.01 0 top
AFTP6543  AFTE14P-GP  [AFTE14P-75]  57.94 31.12 0 top
AFTP6544  AFTE14P-GP  [AFTE14P-75]  58.78 35.82 0 top
AFTP6545  AFTE14P-GP  [AFTE14P-75]  59.9 31.12 0 top
AFTP6546  AFTE14P-GP  [AFTE14P-75]  59.46 34.01 0 top
AFTP6547  AFTE14P-GP  [AFTE14P-75]  60.91 32.74 0 top
AFTP6548  AFTE14P-GP  [AFTE14P-75]  61.95 31.12 0 top
AFTP6549  AFTE14P-GP  [AFTE14P-75]  62.87 32.79 0 top
AFTP6550  AFTE14P-GP  [AFTE14P-75]  61.29 34.62 0 top
AFTP6551  AFTE14P-GP  [AFTE14P-75]  63.88 31.14 0 top
AFTP6552  AFTE14P-GP  [AFTE14P-75]  65.05 32.69 0 top
AFTP6553  AFTE14P-GP  [AFTE14P-75]  64.67 34.67 0 top
AFTP6554  AFTE14P-GP  [AFTE14P-75]  66.25 31.14 0 top
AFTP6555  AFTE14P-GP  [AFTE14P-75]  67.21 32.79 0 top
AFTP6556  AFTE14P-GP  [AFTE14P-75]  69.5 32.69 0 top
AFTP6557  AFTE14P-GP  [AFTE14P-75]  73.08 31.17 0 top
AFTP6558  AFTE14P-GP  [AFTE14P-75]  68.28 31.19 0 top
AFTP6559  AFTE14P-GP  [AFTE14P-75]  67.85 35.03 0 top
AFTP6560  AFTE14P-GP  [AFTE14P-75]  70.74 31.24 0 top
AFTP6561  AFTE14P-GP  [AFTE14P-75]  69.8 34.88 0 top
AFTP6562  AFTE14P-GP  [AFTE14P-75]  72.06 32.82 0 top
AFTP6563  AFTE14P-GP  [AFTE14P-75]  74.02 32.84 0 top
AFTP6564  AFTE14P-GP  [AFTE14P-75]  71.71 34.8 0 top
AFTP6565  AFTE14P-GP  [AFTE14P-75]  75.01 31.19 0 top
AFTP6566  AFTE14P-GP  [AFTE14P-75]  75.97 29.54 0 top
AFTP6567  AFTE14P-GP  [AFTE14P-75]  57.56 34.29 0 top
AFTP6609  AFTE14P-GP  [AFTE14P-75]  127 84.51 180 bottom
AFTP6610  AFTE14P-GP  [AFTE14P-75]  164.95 41.61 0 top
AFTP6611  AFTE14P-GP  [AFTE14P-75]  128.07 114.43 0 top
AFTP6613  AFTE14P-GP  [AFTE14P-75]  201.68 39.07 0 top
AFTP6614  AFTE14P-GP  [AFTE14P-75]  198.5 38.91 0 top
AFTP6615  AFTE14P-GP  [AFTE14P-75]  197.74 36.88 0 top
AFTP6801  AFTE14P-GP  [AFTE14P-75]  17.12 43.77 0 top
AFTP6802  AFTE14P-GP  [AFTE14P-75]  17.12 41.86 0 top
AFTP6803  AFTE14P-GP  [AFTE14P-75]  17.91 40.11 0 top
AFTP7101  AFTE14P-GP  [AFTE14P-75]  15.88 112.47 0 top
AFTP7102  AFTE14P-GP  [AFTE14P-75]  16.79 119.28 0 top
AFTP7301  AFTE14P-GP  [AFTE14P-75]  44.5 127.84 0 top
AFTP7302  AFTE14P-GP  [AFTE14P-75]  10.54 116.26 0 top
AFTP7303  AFTE14P-GP  [AFTE14P-75]  9.4 123.75 0 top
AFTP7304  AFTE14P-GP  [AFTE14P-75]  27.38 117.76 180 bottom
AFTP9201  AFTE14P-GP  [AFTE14P-75]  213.92 65.2 0 top
AFTP9204  AFTE14P-GP  [AFTE14P-75]  133.06 39.57 0 top
BATT1  ACES-CON10-10-GP-U  [88231-1001-LP]  139.7 34 180 bottom
BIOS1  MX25L12872FM2I-10G-GP  [SOIC8-1H86]  130.85 85.12 0 bottom
BIOS2  MX25L6473FZNI-08G-3-GP  [DFN8A5060-G4135H32]  135.66 85.02 180 top
C501  SCD1U16V2KX-3DLGP  [C402H22]  58.65 38.91 0 top
C801  SC1U6D3V1MX-GP  [C0201H14]  91.44 117.04 90 bottom
C802  SC1U6D3V1MX-GP  [C0201H14]  78.49 114.53 270 bottom
C803  SC1U6D3V1MX-GP  [C0201H14]  101.58 72.7 0 top
C804  SC1U6D3V1MX-GP  [C0201H14]  54.05 49.18 180 top
C805  SCD1U16V2KX-3DLGP  [C402H22]  97.03 117.05 270 top
C806  SC1U6D3V1MX-GP  [C0201H14]  97.03 116.28 270 top
C807  SC22U6D3V3MX-1-DL-GP  [C603H40]  97.18 118.04 90 top
C1102  SC1U6D3V1MX-GP  [C0201H14]  69.85 102.13 0 top
C1103  SC1U6D3V1MX-GP  [C0201H14]  65.73 94.95 270 top
C1104  SC1U6D3V1MX-GP  [C0201H14]  70.23 105.02 0 top
C1105  SC1U6D3V1MX-GP  [C0201H14]  67.71 100.14 0 top
C1106  SC1U6D3V1MX-GP  [C0201H14]  75.83 100.8 90 top
C1107  SC1U6D3V1MX-GP  [C0201H14]  72.52 101.78 90 top
C1108  SC1U6D3V1MX-GP  [C0201H14]  96.62 90.83 180 top
C1109  SC1U6D3V1MX-GP  [C0201H14]  85.35 90.86 0 top
C1110  SC1U6D3V1MX-GP  [C0201H14]  95.86 90.83 180 top
C1111  SC1U6D3V1MX-GP  [C0201H14]  84.56 90.86 0 top
C1112  SC22U6D3V3MX-1-DL-GP  [C603H40]  98.3 121.39 270 top
C1113  SC22U6D3V3MX-1-DL-GP  [C603H40]  111.99 89.49 180 top
C1114  SC1U6D3V1MX-GP  [C0201H14]  100.41 99.42 270 top
C1115  SC22U6D3V3MX-1-DL-GP  [C603H40]  106.37 115.4 270 top
C1116  SC1U6D3V1MX-GP  [C0201H14]  113.34 100.03 0 top
C1117  SC1U6D3V1MX-GP  [C0201H14]  98.91 116.77 270 top
C1118  SC22U6D3V3MX-1-DL-GP  [C603H40]  98.3 123.73 270 top
C1119  SC1U6D3V1MX-GP  [C0201H14]  98.89 118.38 270 top
C1120  SC10U6D3V3MX-DL-GP  [C603H36]  98.3 122.56 270 top
C1121  SC1U6D3V1MX-GP  [C0201H14]  100.34 94.69 270 top
C1122  SC22U6D3V3MX-1-DL-GP  [C603H40]  112.95 98.31 180 top
C1123  SC10U6D3V3MX-DL-GP  [C603H36]  113.26 89.49 180 top
C1128  SC22U6D3V3MX-1-DL-GP  [C603H40]  98.3 120.22 270 top
C1129  SC22U6D3V3MX-1-DL-GP  [C603H40]  98.29 124.92 270 top
C1130  SC22U6D3V3MX-1-DL-GP  [C603H40]  74.17 76.13 180 top
C1131  SC22U6D3V3MX-1-DL-GP  [C603H40]  140.72 51.13 180 top
C1132  SC22U6D3V3MX-1-DL-GP  [C603H40]  135.92 51.13 180 top
C1133  SC22U6D3V3MX-1-DL-GP  [C603H40]  107.25 127.66 270 top
C1134  SC22U6D3V3MX-1-DL-GP  [C603H40]  109.1 125.28 90 top
C1135  SC22U6D3V3MX-1-DL-GP  [C603H40]  107.6 126.49 270 top
C1136  SC10U6D3V3MX-DL-GP  [C603H36]  83.65 76.18 180 top
C1137  SC10U6D3V3MX-DL-GP  [C603H36]  91.16 76.23 180 top
C1138  SC10U6D3V3MX-DL-GP  [C603H36]  87.02 76.05 180 top
C1139  SCD1U16V2KX-3DLGP  [C402H22]  124.06 49.25 0 top
C1140  SCD1U16V2KX-3DLGP  [C402H22]  92.46 46.92 0 top
C1141  SCD1U16V2KX-3DLGP  [C402H22]  65.2 48.24 0 top
C1142  SCD1U16V2KX-3DLGP  [C402H22]  131.07 50.62 0 top
C1202  SC10U6D3V3MX-GP  [C603H38]  134.72 51.13 180 top
C1203  SC10U6D3V3MX-GP  [C603H38]  139.5 51.13 180 top
C1204  SC10U6D3V3MX-GP  [C603H38]  132.34 51.13 180 top
C1205  SC10U6D3V3MX-GP  [C603H38]  133.53 51.13 180 top
C1206  SC10U6D3V3MX-GP  [C603H38]  137.13 51.13 180 top
C1207  SC1U6D3V1MX-GP  [C0201H14]  97.06 48.59 0 top
C1208  SC10U6D3V3MX-GP  [C603H38]  74.22 40.11 180 bottom
C1209  SC10U6D3V3MX-GP  [C603H38]  141.91 51.13 180 top
C1210  SC10U6D3V3MX-GP  [C603H38]  138.31 51.13 180 top
C1214  SC1U6D3V1MX-GP  [C0201H14]  132.06 42.93 90 top
C1215  SC1U6D3V1MX-GP  [C0201H14]  141.91 43.31 90 top
C1216  SC1U6D3V1MX-GP  [C0201H14]  141.1 49.05 0 top
C1217  SC1U6D3V1MX-GP  [C0201H14]  152.53 45.01 0 top
C1218  SC1U6D3V1MX-GP  [C0201H14]  161.98 44.76 180 top
C1219  SC1U6D3V1MX-GP  [C0201H14]  133.2 43.28 0 top
C1220  SC1U6D3V1MX-GP  [C0201H14]  136.07 45.62 180 top
C1221  SC1U6D3V1MX-GP  [C0201H14]  139.5 45.21 180 top
C1222  SCD022U16V2KX-3GP  [C402H22]  73.56 40.06 270 top
C1223  SC4D7U6D3V3KX-GP  [C603H36]  97.13 40.82 270 bottom
C1225  SC1U6D3V1MX-GP  [C0201H14]  98.76 40.64 0 top
C1226  SC1U6D3V1MX-GP  [C0201H14]  97.95 40.64 0 top
C1227  SC4D7U6D3V3KX-GP  [C603H36]  95.58 39.63 90 bottom
C1228  SCD1U16V2KX-L-GP  [C402H22]  96.12 47.55 180 top
C1229  SCD1U16V2KX-3DLGP  [C402H22]  72.37 40.54 0 top
C1231  SC10U6D3V2MX-2-GP  [C402-TO0D2H28]  97.92 48.49 0 top
C1301  SCD1U16V2KX-3DLGP  [C402H22]  149 43.56 90 top
C1303  SC10U6D3V3MX-GP  [C603H38]  70.62 76.25 180 top
C1304  SC10U6D3V2MX-2-GP  [C402-TO0D2H28]  59.11 49.05 0 top
C1305  SC10U6D3V3MX-GP  [C603H38]  73.03 40.11 180 bottom
C1306  SC10U6D3V3MX-GP  [C603H38]  137.11 40.64 90 bottom
C1307  SC10U6D3V2MX-2-GP  [C402-TO0D2H28]  67.85 48.08 0 top
C1308  SC10U6D3V3MX-GP  [C603H38]  71.81 40.12 180 bottom
C1309  SC10U6D3V2MX-2-GP  [C402-TO0D2H28]  63.17 49.4 0 top
C1310  SC10U6D3V3MX-GP  [C603H38]  75.42 40.11 180 bottom
C1311  SC10U6D3V2MX-2-GP  [C402-TO0D2H28]  173.79 50.27 90 top
C1313  SC1U6D3V1MX-GP  [C0201H14]  173.76 49.38 90 top
C1315  SC1U6D3V1MX-GP  [C0201H14]  85.78 45.95 0 top
C1316  SC1U6D3V1MX-GP  [C0201H14]  37.36 45.77 0 top
C1317  SC1U6D3V1MX-GP  [C0201H14]  48.97 49 180 top
C1318  SC1U6D3V1MX-GP  [C0201H14]  34.76 45.95 0 top
C1319  SC1U6D3V1MX-GP  [C0201H14]  42.75 44.58 180 top
C1320  SC1U6D3V1MX-GP  [C0201H14]  61.34 45.77 180 top
C1321  SC1U6D3V1MX-GP  [C0201H14]  74.07 49.66 0 top
C1322  SC1U6D3V1MX-GP  [C0201H14]  58.3 45.14 180 top
C1323  SCD022U16V2KX-3GP  [C402H22]  145.55 43.51 270 top
C1324  SC10U6D3V2MX-2-GP  [C402-TO0D2H28]  174.95 44.31 90 top
C1325  SC10U6D3V2MX-2-GP  [C402-TO0D2H28]  174.95 43.4 90 top
C1326  SC1U6D3V1MX-GP  [C0201H14]  175.27 45.96 90 top
C1327  SC1U6D3V1MX-GP  [C0201H14]  174.95 45.19 90 top
C1328  SCD1U16V2KX-L-GP  [C402H22]  173.89 51.52 0 top
C1329  SC2D2U6D3V2MX-DL-GP  [C402H22]  174.67 51.52 0 top
C1603  SCD22U10V2KX-1GP  [C402H22]  109.14 117.41 90 bottom
C1604  SCD22U10V2KX-1GP  [C402H22]  109.14 116.65 90 bottom
C1605  SCD22U10V2KX-1GP  [C402H22]  115.31 118.11 135 bottom
C1606  SCD22U10V2KX-1GP  [C402H22]  114.77 118.66 135 bottom
C1607  SCD22U10V2KX-1GP  [C402H22]  114.92 120.73 135 bottom
C1608  SCD22U10V2KX-1GP  [C402H22]  115.47 120.17 135 bottom
C1611  SCD22U10V2KX-1GP  [C402H22]  106.76 117.74 90 bottom
C1612  SCD22U10V2KX-1GP  [C402H22]  106.76 118.5 90 bottom
C1701  SC220P50V2KX-3DLGP  [C402H22]  160.79 78.79 0 bottom
C1702  SCD22U10V2KX-1GP  [C402H22]  103.63 90.72 270 top
C1703  SCD22U10V2KX-1GP  [C402H22]  86.85 40.17 270 top
C1711  SCD1U16V2KX-3DLGP  [C402H22]  95.73 114.53 270 bottom
C1803  SC12P50V2JN-DL-GP  [C402H22]  120.75 76.73 180 top
C1804  SC12P50V2JN-DL-GP  [C402H22]  120.75 74.68 0 top
C1805  SC1U6D3V1MX-GP  [C0201H14]  166.91 66.33 270 top
C1806  SC1U6D3V1MX-GP  [C0201H14]  169 66.88 90 top
C1807  SC15P50V2JN-DL-GP  [C402H22]  120.2 115.32 90 bottom
C1808  SC15P50V2JN-DL-GP  [C402H22]  116.94 115.29 270 bottom
C1809  SC2D2P50V2CC-DLGP  [C402H22]  122.66 114.48 90 bottom
C2201  SCD1U16V2KX-3DLGP  [C402H22]  100.64 92.9 180 top
C2202  SC1U6D3V1MX-GP  [C0201H14]  105.93 95.3 0 top
C2203  SC1U6D3V1MX-GP  [C0201H14]  105.92 93.93 180 top
C2204  SC1U6D3V1MX-GP  [C0201H14]  107.19 93.93 180 top
C2205  SC1U6D3V1MX-GP  [C0201H14]  106.56 93.93 180 top
C2206  SCD1U16V2KX-3DLGP  [C402H22]  106.94 92.1 270 top
C2207  SCD1U16V2KX-3DLGP  [C402H22]  104.6 92.46 0 top
C2208  SC47U6D3V3MX-2-GP  [C603H40]  104.88 116.58 90 top
C2209  SC1U6D3V1MX-GP  [C0201H14]  104.63 115.72 90 top
C2210  SC1U6D3V1MX-GP  [C0201H14]  107.11 97.38 180 top
C2211  SC1U6D3V1MX-GP  [C0201H14]  113.98 97.64 180 top
C2212  SC1U6D3V1MX-GP  [C0201H14]  98.91 115.16 270 top
C2213  SC1U6D3V1MX-GP  [C0201H14]  103.15 91.72 90 top
C2214  SC1U6D3V1MX-GP  [C0201H14]  103.3 95.63 0 top
C2215  SC1U6D3V1MX-GP  [C0201H14]  98.9 115.97 270 top
C2216  SC1U6D3V1MX-GP  [C0201H14]  100.32 95.49 270 top
C2217  SC1U6D3V1MX-GP  [C0201H14]  98.91 117.56 270 top
C2218  SC4D7U6D3V3KX-DLGP  [C603H36]  112.71 91.26 270 top
C2219  SC1U6D3V1MX-GP  [C0201H14]  115.17 102.95 180 top
C2220  SC22U6D3V3MX-1-DL-GP  [C603H40]  104.75 98.16 90 top
C2221  SCD1U16V2KX-3DLGP  [C402H22]  164.95 66.68 0 top
C2222  SC1U6D3V1MX-GP  [C0201H14]  165.74 66.68 0 top
C2223  SC1U6D3V1MX-GP  [C0201H14]  114.1 100.03 0 top
C2224  SC1U6D3V1MX-GP  [C0201H14]  144.44 71.33 0 top
C2225  SC1U6D3V1MX-GP  [C0201H14]  115.12 89.38 90 top
C2226  SC1U6D3V1MX-GP  [C0201H14]  103.94 92.36 0 top
C2227  SC1U6D3V1MX-GP  [C0201H14]  105.26 92.41 0 top
C2228  SC1U6D3V1MX-GP  [C0201H14]  105.9 92.41 0 top
C2229  SC1U6D3V1MX-GP  [C0201H14]  102.14 91.72 90 top
C2230  SC1U6D3V1MX-GP  [C0201H14]  102.64 92.81 90 top
C2231  SC47U6D3V3MX-2-GP  [C603H40]  114.2 102.74 180 top
C2405  SC100P50V2JN-3GP  [C402H22]  41.53 72.04 90 top
C2406  SCD1U16V2KX-3DLGP  [C402H22]  41.53 72.8 90 top
C2407  SCD1U16V2KX-3DLGP  [C402H22]  39.14 77.22 180 top
C2408  SCD1U16V2KX-3DLGP  [C402H22]  33.33 76.63 180 top
C2409  SCD01U25V2KX-3DLGP  [C402H22]  23.37 63.3 90 bottom
C2410  SCD1U16V2KX-3DLGP  [C402H22]  38.56 57 270 top
C2411  SCD1U16V2KX-3DLGP  [C402H22]  19.56 63.76 90 bottom
C2412  SCD1U16V2KX-3DLGP  [C402H22]  29.47 76.13 270 top
C2413  SCD1U16V2KX-3DLGP  [C402H22]  41.68 66.07 0 top
C2414  SCD1U16V2KX-3DLGP  [C402H22]  36.68 75.87 0 top
C2416  SCD1U16V2KX-3DLGP  [C402H22]  17.78 68.2 270 top
C2418  SC1U6D3V1MX-GP  [C0201H14]  23.93 65.86 90 bottom
C2420  SCD1U16V2KX-3DLGP  [C402H22]  29.75 56.21 90 top
C2421  SCD1U16V2KX-3DLGP  [C402H22]  17.78 68.96 270 top
C2422  SCD1U16V2KX-3DLGP  [C402H22]  20.75 70.89 270 top
C2423  SCD1U16V2KX-3DLGP  [C402H22]  32.95 57.15 270 top
C2424  SC18P50V2JN-1DLGP  [C402H22]  26.24 76.1 90 top
C2425  SC18P50V2JN-1DLGP  [C402H22]  27.79 76.1 270 top
C2426  SC2D2U10V3KX-1DLGP-U  [C603H36]  23.78 76.18 90 top
C2428  SCD1U16V2KX-3DLGP  [C402H22]  26.24 71.81 0 bottom
C2429  SCD1U16V2KX-3DLGP  [C402H22]  23.02 65.38 0 bottom
C2431  SC2200P50V2KX-2GP  [C402H22]  30.69 76.68 180 top
C2432  SCD1U16V2KX-3DLGP  [C402H22]  46.87 56.26 135 top
C2435  SC2200P50V2KX-2GP  [C402H22]  37.57 77.27 180 top
C2501  SC10U6D3V3MX-DL-GP  [C603H36]  129.16 79.2 180 bottom
C2502  SCD1U16V2KX-3DLGP  [C402H22]  128.17 78.77 180 bottom
C2503  SCD47U25V3KX-1GP  [C603H36]  162.21 91.37 270 bottom
C2517  SCD022U16V2KX-3DLGP  [C402H22]  165.91 91.4 0 top
C2525  SC1U6D3V1MX-GP  [C0201H14]  155.1 91.44 90 bottom
C2601  SC10U6D3V2MX-GP-U  [C402-TO0D2H28]  127.28 112.52 315 top
C2602  SCD1U16V2KX-3GP  [C402H22]  127.99 111.35 315 top
C2603  SC2200P50V2KX-2DLGP  [C402H22]  158.65 88.15 0 top
C2604  SC4D7U6D3V3KX-DLGP  [C603H36]  162.56 87.17 270 top
C2605  SCD1U25V2KX-1-DL-GP  [C402H22]  159.41 88.15 0 top
C2606  SC470P50V3JN-2GP  [C603H36]  167.39 78.67 90 bottom
C2607  SC2200P50V2KX-2DLGP  [C402H22]  121.28 118.79 315 top
C2610  SCD1U16V2KX-3DLGP  [C402H22]  129.3 108.34 135 bottom
C2612  SCD1U16V2KX-3GP  [C402H22]  16.92 63.15 180 bottom
C2613  SC100P50V2JN-3DLGP  [C402H22]  17.68 63.15 180 bottom
C2614  SCD1U16V2KX-3DLGP  [C402H22]  128.38 109.3 135 bottom
C2702  SC10U6D3V2MX-2-GP  [C402-TO0D2H28]  23.65 8.59 180 top
C2703  SC10U6D3V2MX-2-GP  [C402-TO0D2H28]  22.96 10.49 270 top
C2704  SCD1U16V2KX-3GP  [C402H22]  30.53 7.82 270 top
C2705  SC2D2U10V3KX-1DLGP-U  [C603H36]  30.94 8.82 270 top
C2706  SCD1U16V2KX-3GP  [C402H22]  22.51 11.86 180 top
C2707  SC10U6D3V3MX-DL-GP  [C603H36]  20.93 11.2 270 top
C2708  SC2D2U10V3KX-1DLGP-U  [C603H36]  32.72 7.77 180 top
C2709  SC2D2U10V3KX-1DLGP-U  [C603H36]  29.16 7.19 0 top
C2710  SC10U6D3V2MX-2-GP  [C402-TO0D2H28]  33.63 10.95 90 top
C2711  SC10U6D3V2MX-2-GP  [C402-TO0D2H28]  33.63 10.03 90 top
C2713  SC10U10V3MX-GP-U  [C603H38]  34.55 12.93 90 top
C2714  SCD1U16V2KX-3GP  [C402H22]  32.46 12.57 180 top
C2715  SC10U6D3V2MX-2-GP  [C402-TO0D2H28]  17.43 14.07 0 top
C2717  SC10U10V3MX-GP-U  [C603H38]  34.55 14.2 90 top
C2718  SCD1U16V2KX-3GP  [C402H22]  32.41 14.07 0 top
C2720  SC10U6D3V3MX-GP  [C603H38]  29.92 19.36 90 top
C2721  SCD1U16V2KX-3GP  [C402H22]  30.66 17.63 90 top
C2722  SC10U6D3V3MX-GP  [C603H38]  25.89 18.95 180 top
C2723  SCD1U16V2KX-3GP  [C402H22]  30.69 18.39 90 top
C2735  SCD1U16V2KX-3DLGP  [C402H22]  22.72 17.92 45 top
C2736  SC10U6D3V3MX-GP  [C603H38]  29.87 21.69 90 top
C2740  SC2D2U10V3KX-L-GP  [C603H36]  29.92 20.52 90 top
C2741  SCD1U16V2KX-3GP  [C402H22]  24.77 17.76 180 top
C2902  SC10U6D3V3MX-GP  [C603H38]  19.74 18.34 180 top
C2907  SC4D7U6D3V3KX-DLGP  [C603H36]  20.58 12.63 270 top
C2908  SC4D7U6D3V3KX-DLGP  [C603H36]  20.58 13.82 270 top
C3102  SCD1U16V2KX-3DLGP  [C402H22]  48.26 79.97 180 top
C3103  SCD1U16V2KX-3DLGP  [C402H22]  45.57 81.69 0 bottom
C3104  SCD1U16V2KX-3DLGP  [C402H22]  100.19 114.88 0 bottom
C3107  SCD1U16V2KX-3DLGP  [C402H22]  49.05 79.97 180 top
C3108  SCD1U16V2KX-3DLGP  [C402H22]  44.45 81.69 270 bottom
C3109  SCD1U16V2KX-3DLGP  [C402H22]  100.95 114.88 0 bottom
C3110  SC4D7U6D3V3KX-DLGP  [C603H36]  45.27 84.86 180 bottom
C3112  SCD1U16V2KX-3DLGP  [C402H22]  48.13 83.92 90 bottom
C3115  SCD1U16V2KX-3DLGP  [C402H22]  44.45 83.28 270 bottom
C3116  SC15P50V2JN-DL-GP  [C402H22]  45.06 87.02 270 top
C3117  SCD1U16V2KX-3DLGP  [C402H22]  48.14 84.68 90 bottom
C3118  SCD1U16V2KX-3DLGP  [C402H22]  48.14 85.47 90 bottom
C3119  SCD1U16V2KX-3DLGP  [C402H22]  46.61 85.57 270 bottom
C3120  SCD1U16V2KX-3DLGP  [C402H22]  43.59 80.93 270 bottom
C3121  SCD1U16V2KX-3DLGP  [C402H22]  44.28 84.76 180 bottom
C3122  SC1U6D3V1MX-GP  [C0201H14]  47.6 86.72 180 bottom
C3123  SCD1U16V2KX-3DLGP  [C402H22]  50.68 86.79 0 bottom
C3124  SC4D7U6D3V3KX-DLGP  [C603H36]  46.54 81.15 0 bottom
C3125  SC15P50V2JN-DL-GP  [C402H22]  46.96 86.99 90 top
C3126  SC1U6D3V1MX-GP  [C0201H14]  44.45 82.48 270 bottom
C3202  SC100P3KV8JN-2-GP  [C1808H56]  24.75 84.05 90 bottom
C3203  SCD01U50V2KX-1DLGP  [C402H22]  39.12 84.25 0 bottom
C3507  SC1U10V2KX-1DLGP  [C402H22]  17.5 33.99 90 bottom
C3516  SCD1U16V2KX-3DLGP  [C402H22]  17.3 33.25 270 top
C3517  SC1U10V2KX-1DLGP  [C402H22]  17.3 34.01 270 top
C3518  SC22U6D3V3MX-1-DL-GP  [C603H40]  17.35 38.15 270 bottom
C3519  SC22U6D3V3MX-1-DL-GP  [C603H40]  16.94 35.61 180 bottom
C3520  SCD1U16V2KX-3DLGP  [C402H22]  22.84 54.18 90 bottom
C3521  SCD1U16V2KX-3DLGP  [C402H22]  22.84 53.42 90 bottom
C3522  SCD1U16V2KX-3DLGP  [C402H22]  22.08 44.93 90 bottom
C3523  SCD1U16V2KX-3DLGP  [C402H22]  22.08 44.15 90 bottom
C3524  SCD1U16V2KX-3DLGP  [C402H22]  16.56 56.87 180 bottom
C3525  SC1U10V2KX-1DLGP  [C402H22]  17.35 56.87 180 bottom
C3526  SC22U6D3V3MX-1-DL-GP  [C603H40]  20.27 56.44 180 bottom
C3527  SC22U6D3V3MX-1-DL-GP  [C603H40]  19.1 56.44 180 bottom
C3602  SCD1U16V2KX-3DLGP  [C402H22]  23.6 54.23 180 top
C4001  SC470P50V2KX-3GP  [C402H22]  44.38 132.28 270 top
C4002  SC470P50V2KX-3GP  [C402H22]  64.24 38.43 90 top
C4004  SC10U25V5KX-DL-GP  [C805H58]  57.28 118.39 225 bottom
C4005  SC10U6D3V3MX-DL-GP  [C603H36]  64.01 38.25 270 bottom
C4006  SC10U6D3V3MX-DL-GP  [C603H36]  108.04 118.92 90 top
C4007  SCD1U16V2KX-3DLGP  [C402H22]  107.16 125.5 270 top
C4008  SC10U6D3V3MX-DL-GP  [C603H36]  99.09 76.79 90 top
C4009  SC10U6D3V3MX-DL-GP  [C603H36]  146.23 71.07 0 top
C4010  SCD1U16V2KX-3DLGP  [C402H22]  100.79 72.7 0 top
C4011  SC470P50V2KX-3GP  [C402H22]  64.24 37.67 90 top
C4012  SC10U6D3V3MX-DL-GP  [C603H36]  116.31 115.37 270 top
C4013  SC10U6D3V3MX-DL-GP  [C603H36]  109.97 117.12 180 top
C4014  SC10U25V5KX-DL-GP  [C805H58]  48.01 81.34 0 bottom
C4015  SC10U6D3V3MX-DL-GP  [C603H36]  64.01 39.42 270 bottom
C4017  SC470P50V2KX-3GP  [C402H22]  44.17 133.05 270 top
C4031  SC1U10V2KX-1DLGP  [C402H22]  110.5 115.22 270 top
C4032  SC1U10V2KX-1DLGP  [C402H22]  108.94 120.4 90 top
C4033  SCD1U25V2KX-1-DL-GP  [C402H22]  110.06 122.48 0 top
C4034  SCD1U25V2KX-1-DL-GP  [C402H22]  113.59 115.19 90 bottom
C4035  SC22U6D3V3MX-1-DL-GP  [C603H40]  106.93 120.14 270 top
C4036  SC22U6D3V3MX-1-DL-GP  [C603H40]  108.76 117.12 180 top
C4041  SC1U10V2KX-1DLGP  [C402H22]  95.71 73.23 180 top
C4043  SC1U6D3V1MX-GP  [C0201H14]  99.52 75.77 90 top
C4301  SC1U50V3KX-1-GP  [C603H36]  26.87 129.02 0 top
C4302  SC1U50V3KX-1-GP  [C603H36]  25.96 123.93 90 top
C4303  SCD01U50V2KX-1DLGP  [C402H22]  32.77 133.35 180 top
C4304  SCD01U50V2KX-1DLGP  [C402H22]  31.25 133.35 180 top
C4305  SCD01U50V2KX-1DLGP  [C402H22]  32.01 133.35 180 top
C4306  SC10U25V5KX-DL-GP  [C805H58]  29.47 133.43 270 top
C4344  SC1KP50V2KX-1DLGP  [C402H22]  41.79 116.48 180 top
C4444  SC1500P50V2KX-2-DL-GP  [C402H22]  35.46 126.47 90 top
C5503  SC4D7U6D3V2MX-1-GP  [C402H22]  214.84 43.82 180 bottom
